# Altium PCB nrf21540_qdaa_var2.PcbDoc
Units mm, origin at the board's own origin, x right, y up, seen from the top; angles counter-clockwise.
Board outline 11.5 x 9 mm, 4 copper layers (Top Layer, Mid Layer 1, Mid Layer 2, Bottom Layer), stack 1.583 mm thick; 10 components, 17 nets, 35 pads, 31 vias.
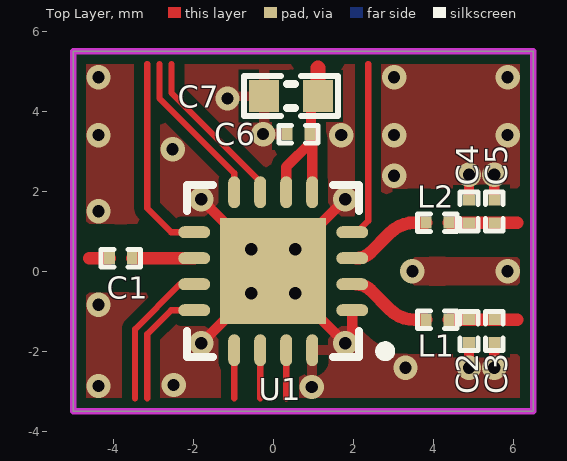
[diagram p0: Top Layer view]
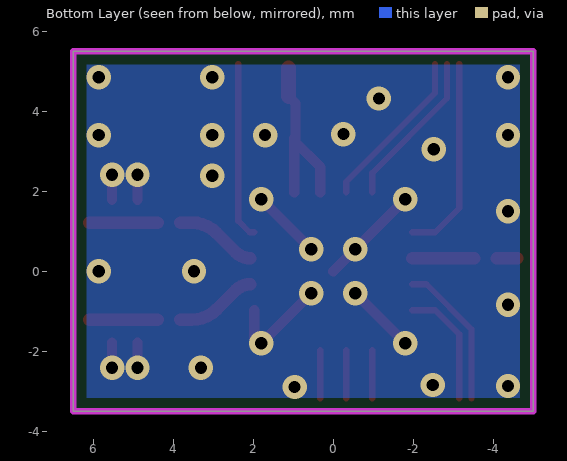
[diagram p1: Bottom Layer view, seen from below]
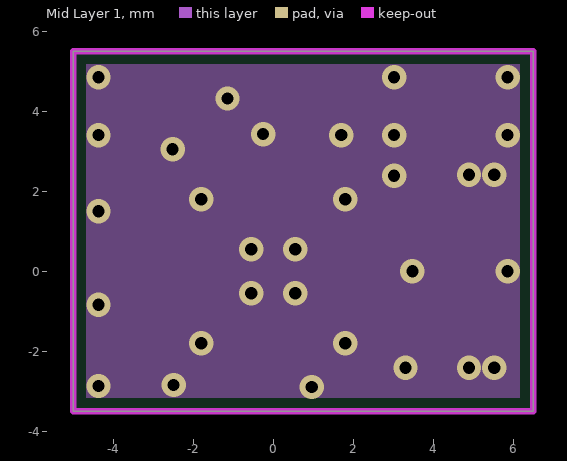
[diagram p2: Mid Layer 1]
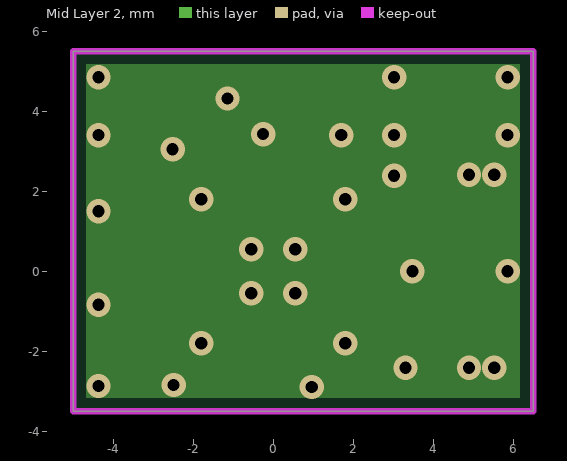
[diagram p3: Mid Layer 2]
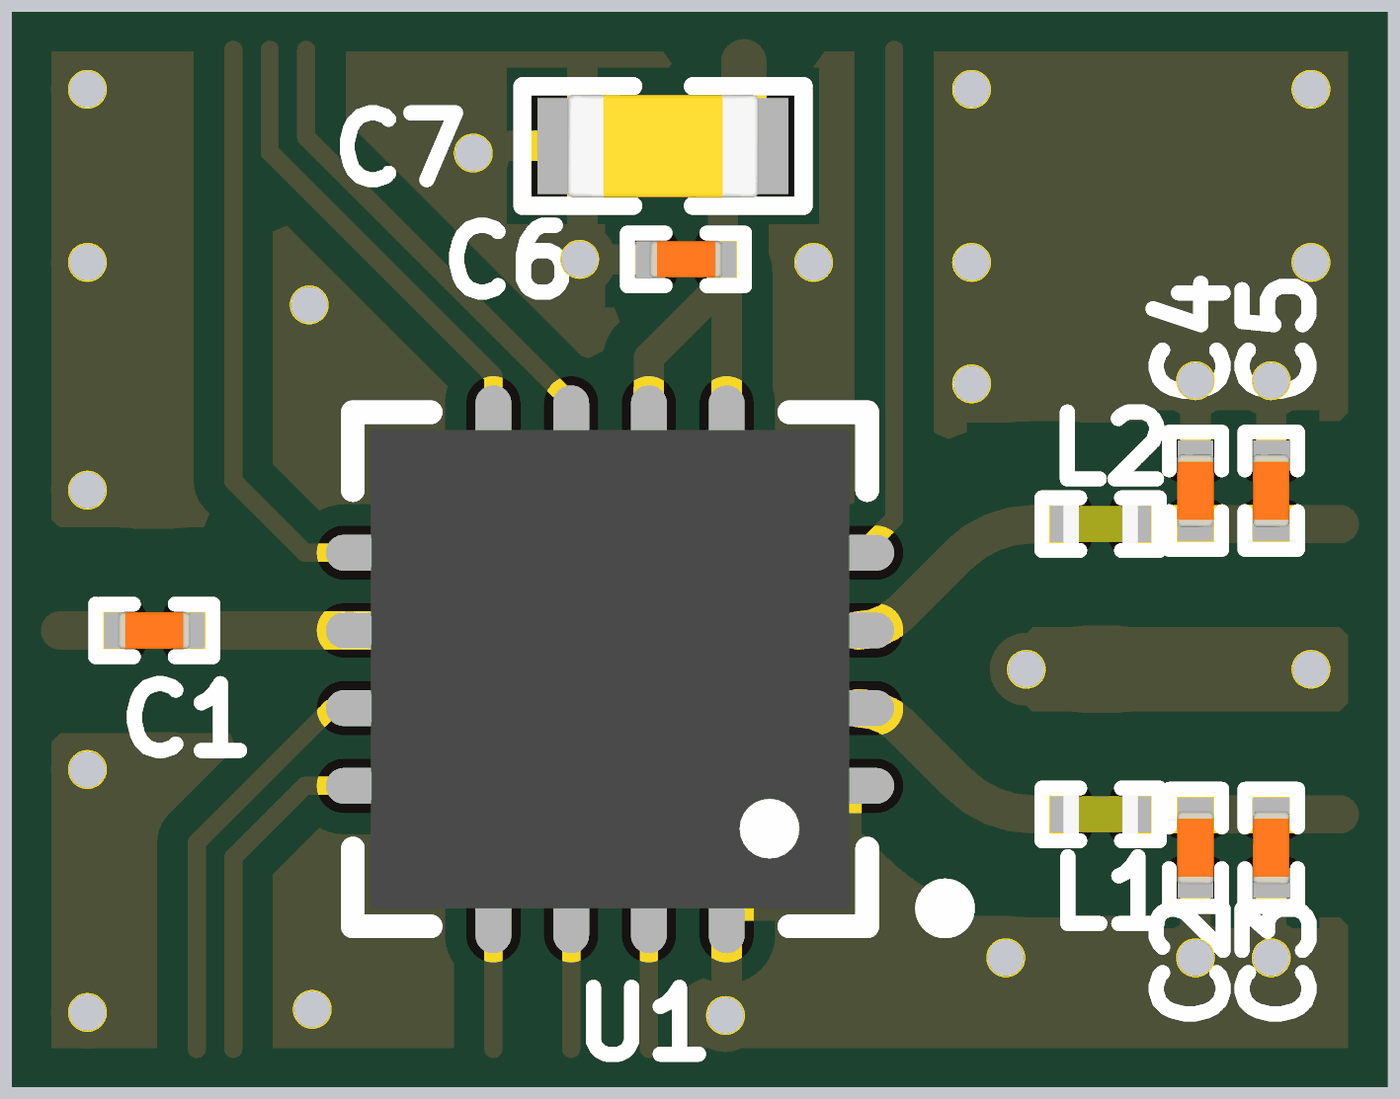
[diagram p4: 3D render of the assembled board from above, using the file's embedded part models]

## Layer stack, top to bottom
Top Solder: solder mask 0.0102, Solder Resist, Dk 3.5
Top Layer: signal copper 0.0356
Dielectric1: core 0.07, FR-4, Dk 4.8
Mid Layer 1: signal copper 0.036
Dielectric 3: prepreg 1.3, Dk 4.2
Mid Layer 2: signal copper 0.036
Dielectric 2: core 0.07, Dk 4.2
Bottom Layer: signal copper 0.0356
Bottom Solder: solder mask 0.0102, Solder Resist, Dk 3.5

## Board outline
-5,-3.5 6.5,-3.5 6.5,5.5 -5,5.5

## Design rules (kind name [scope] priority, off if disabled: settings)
Clearance Polygon_ANT [(InNamedPolygon('Top_Layer-GND')) or  (InNamedPolygon('Mid_Layer_1-GND')) or (InNamedPolygon('Mid_Layer_2-GND')) or (InNamedPolygon('Bottom_Layer-GND')) vs InNet('ANT1') or InNet('ANT2') or InNet('TRX') or InNet('RF_O1') or InNet('RF_O2') or InNet('RF_I') or InNet('A') or InNet('ANT')] p1: gap=0.7 ignorepadtopadclearanceinfootprint=FALSE
Clearance Polygon_RF [(InNamedPolygon('Top_Layer-GND')) or  (InNamedPolygon('Mid_Layer_1-GND')) or (InNamedPolygon('Mid_Layer_2-GND')) or (InNamedPolygon('Bottom_Layer-GND')) vs InNet('RF')] p2: gap=0.254 ignorepadtopadclearanceinfootprint=FALSE
Clearance Polygon [(InNamedPolygon('Top_Layer-GND')) or  (InNamedPolygon('Mid_Layer_1-GND')) or (InNamedPolygon('Mid_Layer_2-GND')) or (InNamedPolygon('Bottom_Layer-GND'))] p3: gap=0.254 ignorepadtopadclearanceinfootprint=FALSE except(0: Arc-Hole Track-Hole SMDPad-Hole THPad-Hole Via-Hole Fill-Hole Poly-Hole Region-Hole Text-Hole)
Clearance Clearance_Top [OnLayer('Top Layer')] p4: gap=0.152 ignorepadtopadclearanceinfootprint=FALSE
Clearance [All] p5: gap=0.152 ignorepadtopadclearanceinfootprint=FALSE
ComponentClearance [All] p1 off: gap=0.254 collisioncheckmode=3 verticalgap=0.254 showdistances=FALSE
FabricationTestPointUsage TestPointUsage [All] p1: valid=0 allowmultiple=FALSE
FabricationTestpoint Testpoint [All] p1: side=3 testpointundercomponent=TRUE minsize=1.016 maxsize=2.54 preferedsize=1.524 minholesize=0 maxholesize=1.016 preferedholesize=0.813 testpointgrid=0.025 allowsidetop=TRUE allowsidebottom=TRUE usegrid=TRUE gridtolerance=0
Height [All] p1 off: minheight=0 maxheight=25.4 prefheight=12.7
HoleSize [All] p1: absolutevalues=TRUE maxlimit=4.064 minlimit=0.1 maxpercent=80.000 minpercent=20.000
MinimumAnnularRing [All] p1 off: minimumring=0.152
PolygonConnect PolygonConnect_1 [isVia and innet(gnd)] p1: connectstyle=Direct reliefconductorwidth=0.254 reliefentries=4 polygonreliefangle="90 Angle" airgapwidth=0.254
PolygonConnect [All] p2: connectstyle=Relief reliefconductorwidth=0.254 reliefentries=4 polygonreliefangle="90 Angle" airgapwidth=0.254
RoutingVias [All] p1: holewidth=0.305 width=0.61 viastyle="Through Hole" minholewidth=0.15 minwidth=0.35 maxholewidth=0.305 maxwidth=0.61
SilkToSolderMaskClearance SilkscreenOverComponentPads [IsPad] p1: minsilkscreentomaskgap=0.254 clearancetoexposedcopper=TRUE
SolderMaskExpansion [All] p1: expansion=0.076
Width [All] p1: maxlimit=2 minlimit=0.152 preferedwidth=0.152 minimp=50.000000 maximp=50.000000 favimp=50.000000
24 further rules are at their usual default settings.

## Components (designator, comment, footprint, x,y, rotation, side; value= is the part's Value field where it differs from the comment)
C1 "1.0pF" CAPC0603X03L_C -3.81,0.325 r0 top
C2 "0.9pF" CAPC0603X03L_C 4.894,-1.493 r90 top
C3 "0.3pF" CAPC0603X03L_C 5.527,-1.493 r90 top
C4 "0.9pF" CAPC0603X03L_C 4.894,1.493 r270 top
C5 "0.3pF" CAPC0603X03L_C 5.527,1.493 r270 top
C6 "100nF" CAPC0603X03L_C 0.635,3.429 r0 top
C7 "10µF" CAPC1608X06L 0.443,4.377 r0 top
L1 "1.9nH" INDC0603X03L_C 4.101,-1.214 r0 top
L2 "1.9nH" INDC0603X03L_C 4.101,1.214 r0 top
U1 "nRF21540-QDAA" QFN65P400X400X65_HS-17N 0,0 r180 top

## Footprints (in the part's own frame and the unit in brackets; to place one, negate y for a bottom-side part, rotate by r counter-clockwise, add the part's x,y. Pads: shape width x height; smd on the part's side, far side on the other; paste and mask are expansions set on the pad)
CAPC0603X03L_C [mm] "Chip Capacitor, 2-Leads, Body 0.6x0.3mm, IPC High Density"
  rect 0.27x0.3 smd: 1(-0.285,0) 2(0.285,0)
  silkscreen extent -0.49,-0.22 0.49,0.22, body extent -0.3,-0.15 0.31,0.15, height 0.3
CAPC1608X06L [mm] "Chip Capacitor, 2-Leads, Body 1.6x0.8mm, IPC High Density"
  rect 0.75x0.8 smd: 1(-0.675,0) 2(0.675,0)
  silkscreen extent -1.17,-0.5 1.17,0.5, body extent -0.8,-0.43 0.8,0.43, height 0.8
INDC0603X03L_C [mm] "Chip Inductor, 2-Leads, Body 0.6x0.3mm, IPC High Density"
  rect 0.27x0.3 smd: 1(-0.285,0) 2(0.285,0)
  silkscreen extent -0.49,-0.22 0.49,0.22, body extent -0.31,-0.16 0.31,0.16, height 0.26
QFN65P400X400X65_HS-17N [mm] "QFN, 16-Leads, Body 4.00x4.00mm, Pitch 0.65mm, Thermal Pad 2.65x2.65mm, IPC Medium Density"
  oval 0.8x0.3 smd: 1(-1.975,0.975) 2(-1.975,0.325) 3(-1.975,-0.325) 4(-1.975,-0.975) 9(1.975,-0.975) 10(1.975,-0.325) 11(1.975,0.325) 12(1.975,0.975)
  oval 0.3x0.8 smd: 5(-0.975,-1.975) 6(-0.325,-1.975) 7(0.325,-1.975) 8(0.975,-1.975) 13(0.975,1.975) 14(0.325,1.975) 15(-0.325,1.975) 16(-0.975,1.975)
  rect 2.65x2.65 smd: 17(0,0)
  silkscreen extent -2.93,-2.15 2.15,2.15, body extent -2,-2 2,2, height 0.65

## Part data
C1: library part C0201-1.0p, "Capacitor, NP0, ±5%"
C2 C4: library part C0201-0.9p, "Capacitor, NP0, ±5%"
C3 C5: library part C0201-0.3p, "Capacitor, NP0, ±5%"
C6: library part C0201-100n, "Capacitor, X7S, ±10%"
C7: library part C0603-10µ, "Capacitor, X7S, ±20%"
L1 L2: library part L0201-1n0, "High frequency chip inductor ±5%", Part Number=L0201-1n9
U1: "Radio front-end / range extender for 2.4GHz"

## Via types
v1: diameter 0.61, hole 0.305, Top Layer to Bottom Layer, tented both sides, 31 vias

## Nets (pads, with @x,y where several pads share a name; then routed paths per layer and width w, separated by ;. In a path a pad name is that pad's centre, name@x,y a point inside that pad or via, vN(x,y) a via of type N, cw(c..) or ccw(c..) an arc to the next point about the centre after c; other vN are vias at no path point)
ANT1: L1.1 U1.2 | length 2
  Top Layer w0.32: U1.2@2.077,-0.325 cw(c2.077,-0.825) 2.43,-0.471 2.916,-0.957 ccw(c3.537,-0.335) 3.537,-1.214 L1.1
ANT2: L2.1 U1.3 | length 2
  Top Layer w0.32: U1.3@2.077,0.325 ccw(c2.077,0.825) 2.43,0.471 2.916,0.957 cw(c3.537,0.335) 3.537,1.214 L2.1
ANT_SEL: U1.8 | length 4
  Top Layer w0.152: -2.845,5.182 -2.845,4.324 -0.975,2.454 U1.8
C\S\N\: U1.15 | length 1.2
  Top Layer w0.152: 0.325,-3.175 U1.15
GND: C2.1 C3.1 C4.1 C5.1 C6.1 C7.1 U1.1 U1.16 U1.17 | length 9.9
  Top Layer w0.254: v1@-1.586,-1.586 v1(-0.55,-0.55) ; v1@-1.586,1.586 v1(-0.55,0.55) U1.17 ; v1(0.55,-0.55) v1@1.586,-1.586 ; v1(0.55,0.55) v1@1.586,1.586 ; v1@1.975,-1.657 U1.1 ; v1(4.894,-2.413) C2.1 ; C4.1 v1(4.894,2.413) ; v1(5.527,-2.413) C3.1 ; C5.1 v1(5.527,2.413)
  other v1: 0.965,-2.896 -4.369,-2.87 -2.489,-2.845 3.308,-2.413 -1.8,-1.8 1.8,-1.8 -4.369,-0.838 3.48,0 5.859,0 -4.369,1.499 -1.8,1.8 1.8,1.8 3.023,2.388 -2.515,3.048 -4.369,3.404 1.702,3.404 3.023,3.404 5.859,3.404 -0.254,3.429 -1.143,4.318 -4.369,4.851 3.023,4.851 5.859,4.851
MISO: U1.14 | length 1.2
  Top Layer w0.152: -0.325,-3.175 U1.14
MODE: U1.4 | length 4.4
  Top Layer w0.152: U1.4 2.093,0.975 2.375,1.257 2.375,5.182
MOSI: U1.13 | length 1.2
  Top Layer w0.152: -0.975,-3.175 U1.13
P\D\N\: U1.11 | length 3.7
  Top Layer w0.152: -3.454,-3.175 -3.454,-1.448 -2.332,-0.325 U1.11
RF_I: C1.1 | length 0.5
  Top Layer w0.32: -4.597,0.325 C1.1
RF_O1: C2.2 C3.2 L1.2 | length 1.7
  Top Layer w0.32: L1.2 6.1,-1.214
RF_O2: C4.2 C5.2 L2.2 | length 1.7
  Top Layer w0.32: L2.2 6.1,1.214
RX_EN: U1.7 | length 4.1
  Top Layer w0.152: -2.54,5.182 -2.54,4.451 -0.325,2.236 U1.7
SCK: U1.12 | length 3
  Top Layer w0.152: -3.15,-3.175 -3.15,-1.574 -2.551,-0.975 U1.12
TRX: C1.2 U1.10 | length 1.5
  Top Layer w0.32: C1.2 U1.10
TX_EN: U1.9 | length 5
  Top Layer w0.152: -3.15,5.182 -3.15,1.574 -2.551,0.975 U1.9
VDD_NRF: C6.2 C7.2 U1.5 U1.6 | length 4.8
  Top Layer w0.254: U1.6 0.325,2.608 0.943,3.226 C6.2@0.943,3.361 ; U1.5 0.975,3.329 C6.2@0.943,3.361 ; C7.2 0.943,4.202 C6.2@0.943,3.361
  Top Layer w0.381: C7.2 1.118,5.08

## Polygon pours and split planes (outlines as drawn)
GND on Bottom Layer "Bottom_Layer-GND" (solid, remove dead copper, pour order 1001): -28.248,10.436 -28.248,-11.564 7.752,-11.564 7.752,10.436
GND on Mid Layer 1 "Mid_Layer_1-GND" (solid, remove dead copper, pour order 1004): -28.248,10.436 -28.248,-11.564 7.752,-11.564 7.752,10.436
GND on Mid Layer 2 "Mid_Layer_2-GND" (solid, remove dead copper, pour order 1002): -28.248,10.436 -28.248,-11.564 7.752,-11.564 7.752,10.436
GND on Top Layer "Top_Layer-GND" (solid, remove dead copper, pour order 1000): -28.248,10.436 -28.248,-11.564 7.752,-11.564 7.752,10.436

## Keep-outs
Keep-Out Layer:
  the board outline again, w0.152

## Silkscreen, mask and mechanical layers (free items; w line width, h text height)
Mechanical 1:
  the board outline again, w0.152

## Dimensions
6.5,-3.5 to 6.5,5.5 on Mechanical 3
6.5,-3.5 to -5,-3.5 on Mechanical 3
